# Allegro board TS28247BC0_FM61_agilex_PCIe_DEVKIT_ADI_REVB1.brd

Outline 274.32 x 111.15 mm; copper layers: TOP, L02_GND1, L03_SIG1, L04_GND2, L05_SIG2, L06_GND3, L07_SIG3, L08_GND4, L09_PWR1, L10_PWR2, L11_GND5, L12_SIG4, L13_GND6, L14_SIG5, L15_GND7, L16_SIG6, L17_GND8, BOTTOM. Coordinates in mm from the lower left corner of the outline.
Outline path: 0,111.15 0,4.5 15,4.5 15,12.75 33.35,12.75 33.35,4.5 41.35,4.5 41.35,10.92 arc(43.18,12.75) 45,10.92 45,0.5 45.5,0 55.7,0 56.2,0.5 56.2,7.45 arc(57.15,8.4) 58.1,7.45 58.1,0.5 58.6,0 128.8,0 129.3,0.5 129.3,7.62 arc(130.67,8.99) 132.04,7.62 132.04,3.45 132.55,2.95 143.35,2.95 144.74,5.32 144.74,7.95 140.78,7.95 arc(139.54,8.46) 139.03,9.7 139.03,11 arc(139.54,12.24) 140.78,12.75 274.32,12.75 274.32,111.15 0,111.15

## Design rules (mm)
constraint set DEFAULT: min track width 0.149
net group AS_CLK: nets AS_CLK AS_CLK_R
net group BUFFER_DIF0_: nets BUFFER_DIF0_N BUFFER_DIF0_P
net group BUFFER_DIF1_: nets BUFFER_DIF1_N BUFFER_DIF1_P
net group CLK_DDR4_CH0_N: nets CLK_DDR4_CH0_N SI5341_OUT3N
net group CLK_DDR4_CH0_P: nets CLK_DDR4_CH0_P SI5341_OUT3P
net group CLK_DDR4_CH1_N: nets CLK_DDR4_CH1_N SI5341_OUT1N
net group CLK_DDR4_CH1_P: nets CLK_DDR4_CH1_P SI5341_OUT1P
net group CLK_DDR4_CH2_N: nets CLK_DDR4_CH2_N SI5341_OUT4N
net group CLK_DDR4_CH2_P: nets CLK_DDR4_CH2_P SI5341_OUT4P
net group CLK_SYS_100M_N: nets CLK_SYS_100M_N SI5341_OUT6N
net group CLK_SYS_100M_P: nets CLK_SYS_100M_P SI5341_OUT6P
net group CLK_SYS_BAK_50M_N: nets CLK_SYS_BAK_50M_N SI5341_OUT7N
net group CLK_SYS_BAK_50M_P: nets CLK_SYS_BAK_50M_P SI5341_OUT7P
net group CORE_PMBUS_ALERTN: nets CORE_PMBUS_ALERTN LTM3888_ALERTN
net group CORE_PMBUS_SCL: nets CORE_PMBUS_SCL LTM3888_SCL
net group CORE_PMBUS_SDA: nets CORE_PMBUS_SDA LTM3888_SDA
net group DP_DDR3B_DQS_6: nets DDR4_DIMM_CH0_DQ43 VSS_SENSE
net group DP_FX2_D_: nets FX2_D_N FX2_D_P
net group DP_PCIE_REFCLK_: nets REFCLK_PCIE_EP_EDGE_N REFCLK_PCIE_EP_EDGE_P
net group DP_PEX_RX_0: nets PCIE_EP_TX_N0 PCIE_EP_TX_P0
net group DP_PEX_RX_1: nets PCIE_EP_TX_N1 PCIE_EP_TX_P1
net group DP_PEX_RX_2: nets PCIE_EP_TX_N2 PCIE_EP_TX_P2
net group DP_PEX_RX_3: nets PCIE_EP_TX_N3 PCIE_EP_TX_P3
net group DP_PEX_RX_4: nets PCIE_EP_TX_N4 PCIE_EP_TX_P4
net group DP_PEX_RX_5: nets PCIE_EP_TX_N5 PCIE_EP_TX_P5
net group DP_PEX_RX_6: nets PCIE_EP_TX_N6 PCIE_EP_TX_P6
net group DP_PEX_RX_7: nets PCIE_EP_TX_N7 PCIE_EP_TX_P7
net group DP_PEX_RX_8: nets PCIE_EP_TX_N8 PCIE_EP_TX_P8
net group DP_PEX_RX_9: nets PCIE_EP_TX_N9 PCIE_EP_TX_P9
net group DP_PEX_RX_10: nets PCIE_EP_TX_N10 PCIE_EP_TX_P10
net group DP_PEX_RX_11: nets PCIE_EP_TX_N11 PCIE_EP_TX_P11
net group DP_PEX_RX_12: nets PCIE_EP_TX_N12 PCIE_EP_TX_P12
net group DP_PEX_RX_13: nets PCIE_EP_TX_N13 PCIE_EP_TX_P13
net group DP_PEX_RX_14: nets PCIE_EP_TX_N14 PCIE_EP_TX_P14
net group DP_PEX_RX_15: nets PCIE_EP_TX_N15 PCIE_EP_TX_P15
net group DP_SI5341_OUT5: nets SI5341_OUT5N SI5341_OUT5P
net group EMMC_CMD: nets EMMC_CMD EMMC_COMMAND
net group EMMC_DAT0: nets EMMC_DAT0 EMMC_DATA0
net group EMMC_DAT1: nets EMMC_DAT1 EMMC_DATA1
net group EMMC_DAT2: nets EMMC_DAT2 EMMC_DATA2
net group EMMC_DAT3: nets EMMC_DAT3 EMMC_DATA3
net group EMMC_DAT4: nets EMMC_DAT4 EMMC_DATA4
net group EMMC_DAT5: nets EMMC_DAT5 EMMC_DATA5
net group EMMC_DAT6: nets EMMC_DAT6 EMMC_DATA6
net group EMMC_DAT7: nets EMMC_DAT7 EMMC_DATA7
net group ENET_GTX_CLK: nets ENET_GTX_CLK N35951471
net group ENET_RX_CLK: nets E_RX_CLK ENET_RX_CLK
net group ENET_RX_DV: nets E_RX_DV ENET_RX_DV
net group ENET_RXD0: nets E_RXD0 ENET_RXD0
net group ENET_RXD1: nets E_RXD1 ENET_RXD1
net group ENET_RXD2: nets E_RXD2 ENET_RXD2
net group ENET_RXD3: nets E_RXD3 ENET_RXD3
net group EXT_JTAG_TCK: nets EXT_JTAG_TCK N37926941
net group FM6_TEMP0: nets FPGA_TEMP0N FPGA_TEMP0P
net group FM6_TEMP1: nets FPGA_TEMP1N FPGA_TEMP1P
net group FM6_TEMP2: nets FPGA_TEMP2N FPGA_TEMP2P
net group FM6_TEMP3: nets FPGA_TEMP3N FPGA_TEMP3P
net group FPGA_OSC_CLK_1: nets FPGA_OSC_CLK_1 SI5341_OUT8P
net group GNDSENSE: nets GNDSENSE VCCLSENSE
net group LTM_SCL: nets LTM_SCL MAIN_I2C_SCL
net group LTM_SDA: nets LTM_SDA MAIN_I2C_SDA
net group MDI_HPS_0: nets MDI_HPS_N0 MDI_HPS_P0
net group MDI_HPS_1: nets MDI_HPS_N1 MDI_HPS_P1
net group MDI_HPS_2: nets MDI_HPS_N2 MDI_HPS_P2
net group MDI_HPS_3: nets MDI_HPS_N3 MDI_HPS_P3
net group N32053041: nets N32052935 N32053041
net group N36803169: nets N36803165 N36803169
net group N36803284: nets N36803267 N36803284
net group PCIE_EP_RX_CN0: nets PCIE_EP_RX_CN0 PCIE_EP_RX_N0
net group PCIE_EP_RX_CN1: nets PCIE_EP_RX_CN1 PCIE_EP_RX_N1
net group PCIE_EP_RX_CN2: nets PCIE_EP_RX_CN2 PCIE_EP_RX_N2
net group PCIE_EP_RX_CN3: nets PCIE_EP_RX_CN3 PCIE_EP_RX_N3
net group PCIE_EP_RX_CN4: nets PCIE_EP_RX_CN4 PCIE_EP_RX_N4
net group PCIE_EP_RX_CN6: nets PCIE_EP_RX_CN6 PCIE_EP_RX_N6
net group PCIE_EP_RX_CN7: nets PCIE_EP_RX_CN7 PCIE_EP_RX_N7
net group PCIE_EP_RX_CN8: nets PCIE_EP_RX_CN8 PCIE_EP_RX_N8
net group PCIE_EP_RX_CN9: nets PCIE_EP_RX_CN9 PCIE_EP_RX_N9
net group PCIE_EP_RX_CN10: nets PCIE_EP_RX_CN10 PCIE_EP_RX_N10
net group PCIE_EP_RX_CN11: nets PCIE_EP_RX_CN11 PCIE_EP_RX_N11
net group PCIE_EP_RX_CN12: nets PCIE_EP_RX_CN12 PCIE_EP_RX_N12
net group PCIE_EP_RX_CN13: nets PCIE_EP_RX_CN13 PCIE_EP_RX_N13
net group PCIE_EP_RX_CN15: nets PCIE_EP_RX_CN15 PCIE_EP_RX_N15
net group PCIE_EP_RX_CP0: nets PCIE_EP_RX_CP0 PCIE_EP_RX_P0
net group PCIE_EP_RX_CP1: nets PCIE_EP_RX_CP1 PCIE_EP_RX_P1
net group PCIE_EP_RX_CP2: nets PCIE_EP_RX_CP2 PCIE_EP_RX_P2
net group PCIE_EP_RX_CP3: nets PCIE_EP_RX_CP3 PCIE_EP_RX_P3
net group PCIE_EP_RX_CP4: nets PCIE_EP_RX_CP4 PCIE_EP_RX_P4
net group PCIE_EP_RX_CP5: nets PCIE_EP_RX_CP5 PCIE_EP_RX_P5
net group PCIE_EP_RX_CP6: nets PCIE_EP_RX_CP6 PCIE_EP_RX_P6
net group PCIE_EP_RX_CP7: nets PCIE_EP_RX_CP7 PCIE_EP_RX_P7
net group PCIE_EP_RX_CP8: nets PCIE_EP_RX_CP8 PCIE_EP_RX_P8
net group PCIE_EP_RX_CP9: nets PCIE_EP_RX_CP9 PCIE_EP_RX_P9
net group PCIE_EP_RX_CP10: nets PCIE_EP_RX_CP10 PCIE_EP_RX_P10
net group PCIE_EP_RX_CP11: nets PCIE_EP_RX_CP11 PCIE_EP_RX_P11
net group PCIE_EP_RX_CP12: nets PCIE_EP_RX_CP12 PCIE_EP_RX_P12
net group PCIE_EP_RX_CP13: nets PCIE_EP_RX_CP13 PCIE_EP_RX_P13
net group PCIE_EP_RX_CP14: nets PCIE_EP_RX_CP14 PCIE_EP_RX_P14
net group PCIE_EP_RX_CP15: nets PCIE_EP_RX_CP15 PCIE_EP_RX_P15
net group PWR_MAX10_JTAG_TCK: nets N31875930 PWR_MAX10_JTAG_TCK
net group PWR_MAX10_JTAG_TDI: nets N31875950 PWR_MAX10_JTAG_TDI
net group PWR_MAX10_JTAG_TDO: nets N31875960 PWR_MAX10_JTAG_TDO
net group PWR_MAX10_JTAG_TMS: nets N31875914 PWR_MAX10_JTAG_TMS
net group REFCLK_PCIE_EP_N: nets REFCLK_PCIE_EP_N SI2202_OUT0N
net group REFCLK_PCIE_EP_P: nets REFCLK_PCIE_EP_P SI2202_OUT0P
net group SI5341_OUT0: nets SI5341_OUT0N SI5341_OUT0P
net group UART_RX: nets N35980126 UART_RX
net group USB_UART_DP: nets USB_UART_DM USB_UART_DP
net group VOSNS-: nets VOSNS+ VOSNS-
net group 5MILS: nets 0P6V_DDR4_VTT_CH23_PG 0P6V_VTT_DDR4_CH01_PG 1P2V_DDR4_CH01_EN 1P2V_DDR4_CH01_PG 1P2V_DDR4_CH23_EN 1P2V_DDR4_CH23_PG 1P2V_PRE_PG 1P8V_EN 1P8V_PRE_PG 2P5V_EN 2P5V_PG 3P3V_EN 3P3V_PG 3P3V_STBY_PG 5V_PG 12V_G1_OV_PG 12V_G1_PG 12V_G1_UV_PG 12V_G2_PG FPGA_I2C_EN FPGA_PMBUS_EN FPGA_VCC_EN FPGA_VCC_PG HPS_I2C_EN IO_1P8V_EN IO_1P8V_PG IO_3P3V_EN MAIN_PMBUS_EN PWR_ENA VCC_HSSI_EN VCC_HSSI_PG VCCFUSEWR_EN VCCFUSEWR_PG VCCH_GXER1_EN VCCH_GXER1_PG VCCL_HPS_EN VCCL_HPS_PG VCCL_SDM_EN VCCL_SDM_PG VCCR_EN VCCR_PG VTT_DDR4_CH01_EN VTT_DDR4_CH23_EN
net group 8MILS: nets N31872869 N31873008 N31873076 N31873164 N31873322 N31873366 N32230759 N32408441 N32411786 TSENSE_ALERTN VCC_SENSE
net group CLK: nets REFCLK_156M_QSFPDD_N REFCLK_156M_QSFPDD_P REFCLK_322M_QSFPDD_N REFCLK_322M_QSFPDD_P REFCLK_PCIE_CH0_N REFCLK_PCIE_CH0_P REFCLK_PCIE_CH2_N REFCLK_PCIE_CH2_P
net group CLK_DDR4_CH3_N: nets CLK_DDR4_CH3_N
net group CLK_DDR4_CH3_P: nets CLK_DDR4_CH3_P
net group CLK_SE: nets CLK125_NDO_LED_MODE CLK_PWR_M10 CLK_UBII_M10 DDR4_DIMM_SCL DDR4_DIMM_SDA DDR4D_SCL DDR4D_SDA FPGA_I2C_SCL FPGA_I2C_SDA FPGA_SDM_SCL FPGA_SDM_SDA FX2_SCL FX2_SDA HPS_I2C_SCL HPS_I2C_SDA HPS_OSC_CLK MAX_SDA PCIE_1V2_CLKREQN PCIE_CLKREQN PCIE_EP_3V3_I2C_SCL PCIE_EP_3V3_I2C_SDA PCIE_EP_I2C_SCL PCIE_EP_I2C_SDA QSFPDD_FPGA_I2C_SCL QSFPDD_FPGA_I2C_SDA QSFPDD_I2C_SCL QSFPDD_I2C_SDA SD_CLK_3.3V USB_T_CLK
net group DDR4_DIMM_CH0_ADD: nets DDR4_DIMM_CH0_CK_N0 DDR4_DIMM_CH0_CK_N1 DDR4_DIMM_CH0_CK_P0 DDR4_DIMM_CH0_CK_P1 DDR4_DIMM_CH0_RZQ
net group DDR4_DIMM_CH1_ADD: nets DDR4_DIMM_CH1_RZQ
net group DDR4_DIMM_CH1_CK_N0: nets DDR4_DIMM_CH1_CK_N1
net group DDR4_DIMM_CH1_CK_P0: nets DDR4_DIMM_CH1_CK_P1
net group DDR4_DIMM_CH2_ADD: nets DDR4_DIMM_CH2_RZQ
net group DDR4_DIMM_CH3_ADD: nets DDR4_DIMM_CH3_RZQ
net group ENET_VDD1.2V: nets N35952937
net group MICTOR_JTAG_TCK: nets HPS_JTAG_TCK
net group MICTOR_JTAG_TDI: nets HPS_JTAG_TDI
net group MICTOR_JTAG_TDO: nets HPS_JTAG_TDO
net group MICTOR_JTAG_TMS: nets HPS_JTAG_TMS
net group PCIE_EP_JTAG_TCK: nets N31093028
net group POWER_ON: nets N32233467 N32408103 POWER_ON
net group PWR: nets 0P6V_VREF_DDR4_CH23 1P2V_DDR4_CH01_AGND 1P2V_DDR4_CH23_AGND ACTIVITY_LED IO_1P8V_AGND LINK_LED LT4625_INTVCC N34525726 N35660053 N35951410 N35951814 N37761614 N37761618 USB_UART_CON_5V VBUS_5V VCCAPLL_AGND VCCH_GXER1_AGND VDD33_OUT1 VREF_B
net group QSFPDD: nets QSFPDD0_RX0_N QSFPDD0_RX0_P QSFPDD0_RX1_N QSFPDD0_RX1_P QSFPDD0_RX4_N QSFPDD0_RX4_P QSFPDD0_RX6_N QSFPDD0_RX6_P QSFPDD0_RX7_N QSFPDD0_RX7_P QSFPDD0_TX2_N QSFPDD0_TX2_P QSFPDD0_TX4_N QSFPDD0_TX4_P QSFPDD0_TX6_N QSFPDD0_TX6_P QSFPDD0_TX7_N QSFPDD0_TX7_P QSFPDD1_RX0_N QSFPDD1_RX0_P QSFPDD1_RX1_N QSFPDD1_RX1_P QSFPDD1_RX3_N QSFPDD1_RX3_P QSFPDD1_RX4_N QSFPDD1_RX4_P QSFPDD1_RX6_N QSFPDD1_RX6_P QSFPDD1_TX0_N QSFPDD1_TX0_P QSFPDD1_TX2_N QSFPDD1_TX2_P QSFPDD1_TX3_N QSFPDD1_TX3_P QSFPDD1_TX4_N QSFPDD1_TX4_P QSFPDD1_TX5_N QSFPDD1_TX5_P QSFPDD1_TX6_N QSFPDD1_TX6_P QSFPDD1_TX7_N QSFPDD1_TX7_P
net group SENSE: nets N31872899 N31873240 N31873414

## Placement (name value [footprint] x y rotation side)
B1  Molex_QSFPDD_Cage  [MOLEX_QSFPDD_CAGE]  40.1 77.59 90 top
B2  Molex_QSFPDD_Cage  [MOLEX_QSFPDD_CAGE]  40.1 52.8 90 top
C1  1uF  [0402]  105.42 104.35 90 bottom
C2  0.1uF  [0402]  105.42 103.46 90 bottom
C3  0.1uF  [0402]  106.31 93.68 270 bottom
C4  10nF  [0402]  144.39 95.86 180 bottom
C5  0.1uF  [0402]  125.69 95.86 180 bottom
C6  10nF  [0402]  142.69 93.04 0 bottom
C7  0.1uF  [0402]  123.15 95.86 180 bottom
C8  10nF  [0402]  142.7 95.86 180 bottom
C9  0.1uF  [0402]  140.98 93.04 0 bottom
C10  10nF  [0402]  119.74 93.02 0 bottom
C11  0.1uF  [0402]  140.14 95.86 180 bottom
C12  10nF  [0402]  126.7 95.86 180 bottom
C13  0.1uF  [0402]  124.85 93.02 0 bottom
C14  10nF  [0402]  117.23 93.04 0 bottom
C15  0.1uF  [0402]  138.44 93.04 0 bottom
C16  100uF  [1206]  127.83 93.68 0 bottom
C17  1uF  [0402]  131.3 97.36 270 bottom
C18  0.1uF  [0402]  65.54 97.49 90 bottom
C19  0.1uF  [0402]  131.33 93.42 270 bottom
C20  100uF  [1206]  116.34 95.76 0 bottom
C21  100uF  [1206]  148.6 96.01 180 bottom
C22  10uF  [1210]  148.6 93.22 0 bottom
C23  10uF  [1210]  111.13 94.41 180 bottom
C24  0.1uF  [0402]  67.06 98 0 bottom
C25  0.1uF  [0402]  138.21 95.86 180 bottom
C26  0.1uF  [0402]  122.28 93.02 0 bottom
C27  10nF  [0402]  145.24 93.02 0 bottom
C28  10nF  [0402]  120.61 95.86 180 bottom
C29  10nF  [0402]  131.33 92.15 270 bottom
C31  0.1uF  [0402]  131.3 96.09 270 bottom
C32  100uF  [1206]  188.35 95.46 0 bottom
C33  10uF  [1210]  182.89 94.59 180 bottom
C34  0.1uF  [0402]  192.03 93.03 0 bottom
C35  10nF  [0402]  191.09 93.03 0 bottom
C37  1uF  [0402]  96.15 104.09 90 bottom
C38  0.1uF  [0402]  96.15 103.08 90 bottom
C39  0.1uF  [0402]  97.04 93.68 270 bottom
C40  10nF  [0402]  145.24 100.64 0 bottom
C41  0.1uF  [0402]  122.28 100.64 0 bottom
C42  10nF  [0402]  125.69 103.48 180 bottom
C43  0.1uF  [0402]  126.7 103.48 180 bottom
C44  10nF  [0402]  142.69 100.66 0 bottom
C45  0.1uF  [0402]  124.85 100.64 0 bottom
C46  10nF  [0402]  120.61 103.48 180 bottom
C47  0.1uF  [0402]  138.21 103.48 180 bottom
C48  10nF  [0402]  119.74 100.64 0 bottom
C49  0.1uF  [0402]  138.44 100.66 0 bottom
C50  10nF  [0402]  117.18 100.64 0 bottom
C51  0.1uF  [0402]  123.15 103.48 180 bottom
C52  100uF  [1206]  127.64 98 0 bottom
C53  1uF  [0402]  131.38 104.98 270 bottom
C54  0.1uF  [0402]  67.44 104.85 90 bottom
C55  0.1uF  [0402]  131.3 99.14 270 bottom
C57  10nF  [0402]  131.3 100.41 270 bottom
C58  0.1uF  [0402]  140.14 103.48 180 bottom
C60  0.1uF  [0402]  131.38 103.71 270 bottom
C61  100uF  [1206]  188.35 103.08 0 bottom
C62  10uF  [1210]  183.01 102.09 180 bottom
C63  0.1uF  [0402]  192.03 100.65 0 bottom
C64  10nF  [0402]  191.09 100.65 0 bottom
C65  100uF  [1206]  148.6 103.33 180 bottom
C66  100uF  [1206]  116.34 103.38 0 bottom
C67  10uF  [1210]  111.26 102.03 180 bottom
C68  10uF  [1210]  148.6 100.41 0 bottom
C69  0.1uF  [0402]  140.98 100.66 0 bottom
C70  10nF  [0402]  142.7 103.48 180 bottom
C71  10nF  [0402]  144.39 103.48 180 bottom
C73  1uF  [0402]  151.52 20.65 180 bottom
C74  0.1uF  [0402]  152.53 20.65 180 bottom
C75  0.1uF  [0402]  152.53 30.69 0 bottom
C76  10nF  [0402]  113.79 30.94 180 bottom
C77  0.1uF  [0402]  136.75 30.91 180 bottom
C78  10nF  [0402]  114.65 27.92 0 bottom
C79  0.1uF  [0402]  133.35 27.92 0 bottom
C80  10nF  [0402]  116.34 30.91 180 bottom
C81  0.1uF  [0402]  118.9 27.92 0 bottom
C82  10nF  [0402]  116.33 27.92 0 bottom
C83  0.1uF  [0402]  134.19 30.91 180 bottom
C84  10nF  [0402]  135.89 27.92 0 bottom
C85  0.1uF  [0402]  120.6 30.91 180 bottom
C86  10nF  [0402]  138.43 27.92 0 bottom
C87  0.1uF  [0402]  132.33 27.92 0 bottom
C88  100uF  [1206]  131.2 30.05 180 bottom
C89  1uF  [0402]  127.73 27.38 90 bottom
C90  0.1uF  [0402]  193.56 26.3 270 bottom
C91  0.1uF  [0402]  127.73 31.32 90 bottom
C92  100uF  [1206]  142.7 28.1 180 bottom
C93  100uF  [1206]  110.37 27.66 0 bottom
C94  10uF  [1210]  110.37 30.56 180 bottom
C95  10uF  [1210]  147.71 29.42 0 bottom
C96  0.1uF  [0402]  120.83 27.92 0 bottom
C97  0.1uF  [0402]  118.06 30.91 180 bottom
C98  10nF  [0402]  141.86 30.91 180 bottom
C99  10nF  [0402]  139.29 30.91 180 bottom
C100  0.1uF  [0402]  191.59 26.3 90 bottom
C101  10nF  [0402]  127.73 32.21 90 bottom
C103  0.1uF  [0402]  127.73 26.49 90 bottom
C104  100uF  [1206]  70.69 28.4 180 bottom
C105  10uF  [1210]  75.95 29.39 0 bottom
C106  0.1uF  [0402]  67.94 30.83 180 bottom
C107  10nF  [0402]  67 30.83 180 bottom
C109  10nF  [0402]  114.65 20.3 0 bottom
C110  0.1uF  [0402]  118.06 23.29 180 bottom
C111  10nF  [0402]  116.33 20.3 0 bottom
C112  0.1uF  [0402]  120.6 23.29 180 bottom
C113  10nF  [0402]  116.34 23.29 180 bottom
C114  0.1uF  [0402]  118.9 20.3 0 bottom
C115  10nF  [0402]  113.79 23.32 180 bottom
C116  0.1uF  [0402]  120.83 20.3 0 bottom
C117  10nF  [0402]  135.89 20.3 0 bottom
C118  0.1uF  [0402]  134.19 23.29 180 bottom
C119  10nF  [0402]  138.43 20.3 0 bottom
C120  0.1uF  [0402]  132.33 20.3 0 bottom
C121  100uF  [1206]  131.2 22.43 180 bottom
C122  1uF  [0402]  127.73 24.72 90 bottom
C123  0.1uF  [0402]  193.56 18.76 270 bottom
C124  0.1uF  [0402]  127.73 23.83 90 bottom
C125  100uF  [1206]  110.37 20.04 0 bottom
C126  100uF  [1206]  142.7 20.48 180 bottom
C127  10uF  [1210]  110.37 22.94 180 bottom
C128  10uF  [1210]  147.84 21.8 0 bottom
C129  0.1uF  [0402]  136.75 23.29 180 bottom
C130  0.1uF  [0402]  133.35 20.3 0 bottom
C131  10nF  [0402]  141.86 23.29 180 bottom
C132  10nF  [0402]  139.29 23.29 180 bottom
C133  0.1uF  [0402]  191.59 18.76 90 bottom
C134  10nF  [0402]  129.04 18.11 270 bottom
C136  0.1uF  [0402]  127.73 19.76 90 bottom
C137  100uF  [1206]  70.87 20.78 180 bottom
C138  10uF  [1210]  75.95 21.8 0 bottom
C139  0.1uF  [0402]  67.95 23.19 180 bottom
C140  10nF  [0402]  67.01 23.19 180 bottom
C142  0.1uF  [0402]  44.08 66.37 0 bottom
C143  22uF  [0603]  44.33 68.91 90 bottom
C144  0.1uF  [0402]  56.52 67.01 180 bottom
C145  10uF  [0603]  55 67.01 90 bottom
C146  22uF  [0603]  53.22 65.36 90 bottom
C147  22uF  [0603]  50.81 65.36 90 bottom
C148  0.1uF  [0402]  51.82 69.17 0 bottom
C149  10uF  [0603]  46.87 68.15 0 bottom
C150  22uF  [0603]  46.87 69.93 0 bottom
C151  22uF  [0603]  50.55 69.17 270 bottom
C152  0.1uF  [0402]  57.41 70.18 0 bottom
C153  10uF  [0603]  56.01 70.82 270 bottom
C154  22uF  [0603]  54.49 75.39 180 bottom
C155  22uF  [0603]  54.49 73.87 180 bottom
C156  1000pF  [1206]  19.82 57.99 270 bottom
C157  0.1uF  [0402]  44.08 41.61 0 bottom
C158  22uF  [0603]  44.33 44.15 90 bottom
C159  0.1uF  [0402]  56.17 42.34 180 bottom
C160  10uF  [0603]  55 42.24 90 bottom
C161  22uF  [0603]  50.6 40.52 90 bottom
C162  22uF  [0603]  53.22 40.59 90 bottom
C163  0.1uF  [0402]  50.81 44.4 0 bottom
C164  10uF  [0603]  49.41 44.53 270 bottom
C165  22uF  [0603]  46.87 43.39 0 bottom
C166  22uF  [0603]  46.87 44.91 0 bottom
C167  0.1uF  [0402]  57.41 45.42 0 bottom
C168  10uF  [0603]  56.01 46.05 270 bottom
C169  22uF  [0603]  54.49 49.1 180 bottom
C170  22uF  [0603]  54.49 50.62 180 bottom
C171  1000pF  [1206]  24.39 53.42 90 bottom
C172  0.22uF  [0402]  62.66 10.98 0 bottom
C173  1uF  [0402]  80.14 20.65 180 bottom
C174  0.1uF  [0402]  81.03 20.65 180 bottom
C175  0.22uF  [0402]  63.66 10.98 0 bottom
C176  0.1uF  [0402]  81.03 30.56 0 bottom
C177  0.22uF  [0402]  67.66 10.98 0 bottom
C178  0.22uF  [0402]  68.66 10.98 0 bottom
C179  0.22uF  [0402]  71.66 10.98 0 bottom
C180  0.22uF  [0402]  72.66 10.98 0 bottom
C181  0.22uF  [0402]  75.66 10.98 0 bottom
C182  0.22uF  [0402]  76.66 10.98 0 bottom
C183  0.22uF  [0402]  81.66 10.98 0 bottom
C184  0.22uF  [0402]  82.66 10.98 0 bottom
C185  0.22uF  [0402]  85.66 10.98 0 bottom
C186  0.22uF  [0402]  86.66 10.98 0 bottom
C187  0.22uF  [0402]  89.66 10.98 0 bottom
C188  0.22uF  [0402]  90.66 10.98 0 bottom
C189  0.22uF  [0402]  93.66 10.98 0 bottom
C190  0.22uF  [0402]  94.66 10.98 0 bottom
C191  0.22uF  [0402]  98.66 10.98 0 bottom
C192  0.22uF  [0402]  99.66 10.98 0 bottom
C193  0.22uF  [0402]  102.66 10.98 0 bottom
C194  0.22uF  [0402]  103.66 10.98 0 bottom
C195  0.22uF  [0402]  106.66 10.98 0 bottom
C196  0.22uF  [0402]  107.66 10.98 0 bottom
C197  0.22uF  [0402]  110.66 10.98 0 bottom
C198  0.22uF  [0402]  111.66 10.98 0 bottom
C199  0.22uF  [0402]  114.66 10.98 0 bottom
C200  0.22uF  [0402]  115.66 10.98 0 bottom
C201  0.22uF  [0402]  118.66 10.98 0 bottom
C202  0.22uF  [0402]  119.66 10.98 0 bottom
C203  0.22uF  [0402]  122.66 10.98 0 bottom
C204  0.22uF  [0402]  123.66 10.98 0 bottom
C205  0.22uF  [0402]  126.66 10.98 0 bottom
C206  0.22uF  [0402]  127.66 10.98 0 bottom
C207  0.1uF  [0402]  209.01 32.09 0 bottom
C208  0.1uF  [0402]  208.01 29.49 0 bottom
C209  0.1uF  [0402]  203.33 28.08 0 bottom
C210  0.1uF  [0402]  2.93 88.47 270 bottom
C211  10nF  [0402]  12.33 90.25 90 bottom
C212  10nF  [0402]  12.33 89.23 90 bottom
C213  10nF  [0402]  19.57 80.6 270 bottom
C214  10nF  [0402]  21.34 80.6 270 bottom
C215  0.1uF  [0402]  2.93 91.14 90 bottom
C216  22uF  [0603]  35.06 82.63 270 bottom
C217  0.1uF  [0402]  25.79 88.39 180 top
C218  0.1uF  [0402]  32.01 92.03 180 bottom
C219  22uF  [0603]  15.5 76.91 270 bottom
C220  0.1uF  [0402]  25.5 86.2 0 top
C221  0.1uF  [0402]  26.9 84.8 0 top
C222  0.1uF  [0402]  29.73 87.71 90 top
C223  22uF  [0603]  17.79 80.85 270 bottom
C224  10nF  [0402]  24.45 87.54 270 top
C225  120pF  [0402]  49.28 93.93 180 bottom
C226  10nF  [0402]  36.96 92.03 0 bottom
C227  10nF  [0402]  39.76 91.98 180 bottom
C228  10nF  [0402]  38.87 91.98 180 bottom
C229  22uF  [0603]  55.38 91.77 180 bottom
C230  22uF  [0603]  27.99 88.74 270 top
C231  10nF  [0402]  26.68 88.39 180 top
C232  10nF  [0402]  29.73 89.99 270 top
C233  22uF  [0603]  52.33 91.77 0 bottom
C234  2.2uF  [0603]  52.33 91.77 0 top
C235  1nF  [0402]  56.52 96.47 180 bottom
C236  22uF  [0603]  38.11 82.63 270 bottom
C237  0.1uF  [0402]  29.73 84.91 90 top
C238  0.1uF  [0402]  28.17 84.8 0 top
C239  0.1uF  [0402]  29.73 88.6 90 top
C240  0.1uF  [0402]  29.73 86.69 90 top
C241  0.1uF  [0402]  29.73 83.96 90 top
C242  0.1uF  [0402]  25.5 84.16 180 top
C243  0.1uF  [0402]  28.84 66.37 270 bottom
C244  0.1uF  [0402]  15.5 70.44 180 bottom
C245  39pF  [0402]  22.66 74.63 270 bottom
C246  39pF  [0402]  20.76 74.63 90 bottom
C247  0.1uF  [0402]  26.68 75.01 0 bottom
C248  DNI  [0402]  14.1 104.6 0 bottom
C249  0.1uF  [0402]  24.14 75.39 180 bottom
C250  2.2uF  [0603]  25.41 75.52 90 bottom
C251  0.1uF  [0402]  16.26 68.91 270 bottom
C252  2.2uF  [0603]  18.8 66.75 0 bottom
C253  22uF  [0603]  28.84 74.25 0 bottom
C254  0.1uF  [0402]  25.03 71.07 90 bottom
C255  4.7uF  [0805]  28.07 69.42 270 bottom
C256  10nF  [0402]  17.91 107.01 0 bottom
C257  22uF  [0603]  17.91 104.47 180 bottom
C258  0.1uF  [0402]  47.25 90.63 0 bottom
C259  0.1uF  [0402]  38.74 98.5 90 bottom
C260  0.1uF  [0402]  49.79 98.12 90 bottom
C261  2.2uF  [0603]  40.52 94.95 270 bottom
C262  0.1uF  [0402]  38.74 95.96 90 bottom
C263  0.1uF  [0402]  41.16 107.65 180 bottom
C264  2.2uF  [0603]  46.49 106.12 270 bottom
C265  1uF  [0603]  30.36 108.28 0 bottom
C266  0.1uF  [0402]  28.33 108.28 180 bottom
C267  2.2uF  [0603]  40.52 98.12 270 bottom
C268  0.22uF  [0402]  34.04 92.03 180 bottom
C269  0.22uF  [0402]  28.2 92.41 270 bottom
C270  2.2uF  [0603]  39.76 107.65 90 bottom
C271  0.22uF  [0402]  39.76 104.66 0 bottom
C272  0.22uF  [0402]  38.23 104.22 270 bottom
C273  0.22uF  [0402]  38.23 105.06 270 bottom
C274  0.1uF  [0402]  111.01 62.18 120 bottom
C275  1uF  [0201]  129.33 59.1 150 bottom
C276  1uF  [0201]  127.6 59.1 150 bottom
C277  1uF  [0201]  103.96 64.1 210 bottom
C278  1uF  [0201]  108.55 70.75 210 bottom
C279  1uF  [0201]  108.85 72.28 90 bottom
C280  1uF  [0201]  127.9 51.51 270 bottom
C281  1uF  [0201]  128.21 53.1 30 bottom
C282  1uF  [0201]  103.09 60.6 30 bottom
C283  1uF  [0201]  103.09 59.6 30 bottom
C284  0.1uF  [0402]  122.23 72.65 300 bottom
C285  0.1uF  [0402]  120.49 72.65 300 bottom
C286  0.1uF  [0402]  104.08 72.01 90 bottom
C287  0.1uF  [0402]  104.08 72.8 90 bottom
C289  1uF  [0201]  129.07 52.6 210 bottom
C290  1uF  [0201]  129.33 51.1 330 bottom
C291  1uF  [0201]  107.68 71.6 150 bottom
C292  1uF  [0201]  107.68 72.6 150 bottom
C293  1uF  [0201]  131.91 53.24 30 bottom
C294  0.1uF  [0402]  111.06 51.21 120 bottom
C295  0.1uF  [0402]  109.33 51.21 120 bottom
C296  0.1uF  [0402]  120.49 51.21 240 bottom
C297  0.1uF  [0402]  122.23 51.21 240 bottom
C298  1uF  [0402]  47.07 29.06 180 bottom
C299  1uF  [0402]  46.18 29.06 180 bottom
C300  1uF  [0402]  52.18 22.91 0 bottom
C301  1uF  [0402]  52.97 28.27 180 bottom
C302  1uF  [0402]  47.51 22.91 0 bottom
C303  1uF  [0402]  51.85 25.73 90 bottom
C304  1uF  [0402]  42.62 22.3 180 bottom
C305  1uF  [0402]  44.84 23.07 270 bottom
C306  1uF  [0402]  44.84 24.08 270 bottom
C307  1uF  [0402]  51.7 29.03 180 bottom
C308  1uF  [0402]  51.85 24.46 90 bottom
C309  1uF  [0402]  53.09 22.91 0 bottom
C310  1uF  [0402]  50.98 22.91 0 bottom
C311  1uF  [0402]  50.48 29.06 180 bottom
C312  1uF  [0402]  48.52 29.06 180 bottom
C313  1uF  [0402]  49.54 22.91 0 bottom
C314  1uF  [0402]  51.85 26.62 90 bottom
C315  0.1uF  [0402]  48.66 19.25 0 top
C316  0.1uF  [0402]  47.65 19.25 0 top
C317  0.1uF  [0402]  55.51 27.13 90 top
C318  0.1uF  [0402]  55.51 26.11 90 top
C319  18pF  [0402]  213.75 102.69 0 top
C320  0.1uF  [0402]  209.86 105.34 180 bottom
C321  0.1uF  [0402]  211.46 101.42 270 bottom
C322  0.1uF  [0402]  212.35 104.6 0 bottom
C323  0.1uF  [0402]  209.68 102.44 270 bottom
C324  18pF  [0402]  213.75 104.47 180 top
C325  4.7uF  [0402]  39.12 47.01 0 bottom
C326  0.1uF  [0402]  38.11 47.01 0 bottom
C327  0.1uF  [0402]  27.06 49.48 270 bottom
C328  0.1uF  [0402]  31.12 49.48 90 bottom
C329  0.1uF  [0402]  19.18 49.48 90 bottom
C330  0.1uF  [0402]  15.12 49.48 270 bottom
C331  0.1uF  [0402]  21.09 49.48 270 bottom
C332  0.1uF  [0402]  25.15 49.48 90 bottom
C333  0.1uF  [0402]  91.07 93.68 270 bottom
C334  0.1uF  [0402]  90.56 103.58 180 bottom
C335  0.1uF  [0402]  269.5 64.47 180 bottom
C336  1000pF  [0402]  265.56 59.13 90 bottom
C337  1000pF  [0402]  264.68 55.07 90 bottom
C338  1000pF  [0402]  264.68 51.01 90 bottom
C339  DNI  [1206]  263.18 104.32 270 bottom
C340  0.1uF  [0402]  21.01 30.43 0 top
C341  4.7nF  [0402]  3.03 18.37 180 bottom
C342  12pF  [0402]  13.79 20.6 90 top
C343  12pF  [0402]  11.95 20.6 270 top
C344  0.1uF  [0402]  32.77 45.16 90 bottom
C345  0.1uF  [0402]  10.87 28.86 270 bottom
C346  22uF  [0603]  9.91 19.38 270 top
C347  0.1uF  [0402]  9.66 24.34 0 bottom
C348  0.1uF  [0402]  10.23 29.82 270 bottom
C349  0.1uF  [0402]  16.11 30.18 180 bottom
C350  0.1uF  [0402]  18.61 29.32 90 bottom
C351  0.1uF  [0402]  18.61 24.32 90 bottom
C352  0.1uF  [0402]  16.11 22.37 0 bottom
C353  0.1uF  [0402]  14.36 23.64 0 bottom
C354  0.1uF  [0402]  12.07 23.64 0 bottom
C355  DNI  [0402]  35.44 29.72 180 bottom
C356  10uF  [0603]  22.23 30.43 0 bottom
C357  0.1uF  [0402]  28.03 24.42 90 bottom
C358  0.1uF  [0402]  32.03 26.75 270 bottom
C359  0.1uF  [0402]  32.83 27.71 270 bottom
C360  0.1uF  [0402]  34.43 24.83 45 bottom
C361  0.1uF  [0402]  31.23 25.06 90 bottom
C362  0.1uF  [0402]  36.33 29.72 0 bottom
C363  0.1uF  [0402]  22.36 29.03 90 bottom
C364  0.1uF  [0402]  26.43 28.55 270 bottom
C365  0.1uF  [0402]  32.83 20.42 270 bottom
C366  0.1uF  [0402]  30.51 17.62 90 bottom
C367  0.1uF  [0402]  30.83 20.02 180 bottom
C368  10uF  [0603]  28.09 29.86 0 bottom
C369  0.1uF  [0402]  26.03 24.82 0 bottom
C370  0.1uF  [0402]  35.23 22.82 270 bottom
C371  0.1uF  [0402]  31.63 23.23 0 bottom
C372  0.1uF  [0402]  26.03 27.22 0 bottom
C373  0.1uF  [0402]  31.88 29.72 0 bottom
C374  0.1uF  [0402]  26.03 22.42 180 bottom
C375  0.1uF  [0402]  36.84 28.32 90 bottom
C376  0.1uF  [0402]  34.43 26.83 270 bottom
C377  0.1uF  [0402]  29.63 26.03 270 bottom
C378  0.1uF  [0402]  28.83 22.03 90 bottom
C379  0.1uF  [0402]  37.23 20.82 180 bottom
C380  10uF  [0603]  24.65 25.48 90 bottom
C381  0.1uF  [0402]  37.23 23.23 180 bottom
C382  0.1uF  [0402]  253.63 36.02 0 bottom
C383  1pF  [0402]  255.66 36.02 0 bottom
C384  1pF  [0402]  255.66 34.11 0 bottom
C385  1pF  [0402]  257.69 36.02 0 bottom
C386  1pF  [0402]  251.59 36.02 0 bottom
C387  1pF  [0402]  259.72 36.02 0 bottom
C388  1pF  [0402]  257.69 34.11 0 bottom
C389  1pF  [0402]  259.72 34.11 0 bottom
C390  1pF  [0402]  251.59 34.11 0 bottom
C391  1pF  [0402]  253.63 34.11 0 bottom
C393  0.1uF  [0402]  249.44 65.23 270 top
C394  10uF  [0603]  247.68 67.29 0 top
C395  100pF  [0402]  74.3 81.49 270 top
C396  0.1uF  [0402]  73.03 88.03 180 bottom
C397  10uF  [0603]  262.29 33.48 270 bottom
C398  0.1uF  [0402]  254.95 31.06 0 bottom
C399  0.1uF  [0402]  250.95 26.26 0 bottom
C400  0.1uF  [0402]  247.66 24.59 270 bottom
C401  0.1uF  [0402]  253.35 23.86 0 bottom
C402  0.1uF  [0402]  251.21 20.91 0 bottom
C403  0.1uF  [0402]  260.23 29.29 90 bottom
C404  0.1uF  [0402]  257.75 26.66 90 bottom
C405  10uF  [0603]  257.75 21.41 180 bottom
C406  10uF  [0603]  254.64 21.41 180 bottom
C407  0.1uF  [0402]  260.23 22.18 90 bottom
C408  0.1uF  [0402]  256.55 29.46 0 bottom
C409  0.1uF  [0402]  252.23 20.91 0 bottom
C410  0.1uF  [0402]  247.66 28.65 270 bottom
C411  0.1uF  [0402]  254.55 27.46 270 bottom
C412  0.1uF  [0402]  250.55 28.26 270 bottom
C413  0.1uF  [0402]  255.35 24.26 90 bottom
C414  0.1uF  [0402]  260.23 26.24 90 bottom
C415  0.1uF  [0402]  247.66 32.72 270 bottom
C416  0.1uF  [0402]  252.47 30.26 0 bottom
C417  680pF  [0402]  265.79 89.08 90 bottom
C418  1uF  [0402]  265.79 88.22 270 bottom
C419  22uF  [1206]  238.94 101.55 270 bottom
C420  4.7nF  [0402]  247.25 97.73 0 bottom
C421  560uF  [8MM_CAN]  205.4 71.02 0 top
C422  22uF  [1206]  236.94 101.53 270 bottom
C423  22uF  [1206]  243.06 101.63 270 bottom
C424  22uF  [1206]  241.03 101.58 270 bottom
C425  DNI  [7343P]  251.86 100.99 90 top
C426  4.7nF  [0402]  247.1 91.11 90 top
C427  1.5uF  [1206]  247.3 84.1 180 bottom
C428  150uF  [7343P]  240.6 89.18 270 top
C429  150uF  [7343P]  246.95 100.66 90 top
C430  150uF  [7343P]  242.04 100.99 90 top
C431  150uF  [7343P]  198.59 71.3 270 top
C432  0.01uF  [0402]  240.62 84.66 180 bottom
C433  150uF  [7343P]  258.33 71.71 270 top
C434  4.7nF  [0402]  251.59 78.16 90 bottom
C435  DNI  [7343P]  245.07 81.03 180 top
C436  150uF  [7343P]  247.53 72.72 270 top
C437  150uF  [7343P]  242.2 72.72 270 top
C438  150uF  [7343P]  244.69 59.5 0 top
C439  150uF  [7343P]  252.86 72.72 270 top
C440  150uF  [7343P]  247.53 72.72 270 bottom
C441  150uF  [7343P]  218.12 57.69 270 top
C442  0.1uF  [0402]  254.9 55.96 0 top
C443  1uF  [0402]  247.91 55.22 90 bottom
C444  0.1uF  [0402]  245.24 54.56 0 bottom
C445  22uF  [1206]  250.83 55.58 90 bottom
C446  22uF  [1206]  250.83 55.58 90 top
C447  22uF  [1206]  253.37 55.58 90 top
C448  12pF  [0402]  240.93 50.76 270 bottom
C449  47uF  [1206]  250.83 50.75 90 bottom
C450  47uF  [1206]  253.37 50.75 90 bottom
C451  47uF  [1206]  253.37 50.75 90 top
C452  47uF  [1206]  250.83 50.75 90 top
C453  100pF  [0402]  245.37 49.53 90 top
C454  0.1uF  [0402]  240.93 51.67 270 bottom
C455  DNI  [C0402]  242.64 48.08 90 top
C456  22uF  [0603]  251.21 39.7 0 top
C457  22uF  [0603]  28.54 42.99 270 bottom
C458  47pF  [0402]  258.22 42.05 0 top
C459  47pF  [0402]  26.76 37.02 270 bottom
C460  22uF  [0603]  254.26 38.18 180 top
C461  22uF  [0603]  254.26 39.58 180 bottom
C462  22uF  [0603]  254.26 39.7 180 top
C463  22uF  [0603]  28.54 39.94 90 bottom
C464  22uF  [0603]  30.11 39.96 90 bottom
C465  22uF  [0603]  30.11 43 270 bottom
C466  10nF  [0402]  252.2 44.73 90 top
C467  10nF  [0402]  23.63 43.89 90 bottom
C555  22uF  [0603]  211.46 53.5 180 top
C557  47pF  [0402]  205.25 51.81 180 top
C558  22uF  [0603]  205.8 53.42 180 bottom
C559  22uF  [0603]  208.64 53.42 0 bottom
C560  22uF  [0603]  205.8 53.42 180 top
C561  10nF  [0402]  211.21 49.05 270 top
C652  2.2uF  [0402]  50.55 107.39 90 bottom
C653  22uF  [0603]  52.71 100.41 180 bottom
C654  22uF  [0603]  55.89 100.41 0 bottom
C655  22uF  [0603]  55.89 101.93 0 bottom
C656  22uF  [0603]  55.89 105.11 0 bottom
C657  22uF  [0603]  55.89 106.76 0 bottom
C658  0.1uF  [0402]  48.65 102.06 180 bottom
C659  22uF  [0603]  55.89 103.46 0 bottom
C660  10nF  [0402]  52.97 108.16 90 bottom
C661  2.2uF  [0402]  208.6 17.14 270 bottom
C662  22uF  [0603]  203.26 24 180 top
C663  22uF  [0603]  203.26 22.47 180 bottom
C664  22uF  [0603]  203.26 22.47 180 top
C665  22uF  [0603]  203.26 20.95 180 top
C666  22uF  [0603]  203.26 24 180 bottom
C667  22uF  [0603]  206.44 24 0 top
C668  22uF  [0603]  203.26 19.3 180 bottom
C669  22uF  [0603]  203.26 17.65 180 bottom
C670  22uF  [0603]  206.44 24 0 bottom
C671  22uF  [0603]  203.26 20.95 180 bottom
C672  0.1uF  [0402]  210.95 22.22 0 bottom
C673  10nF  [0402]  207.2 16.25 270 bottom
C679  100uF  [B2]  40.77 65.23 270 bottom
C680  DNI  [1210]  37.22 65.23 270 bottom
C681  0.047uF  [0402]  34.61 68.53 90 bottom
C682  22uF  [0603]  20.28 42.99 270 bottom
C683  270pF  [0402]  18.5 37.04 270 bottom
C684  22uF  [0603]  21.85 43 270 bottom
C685  22uF  [0603]  21.85 39.96 90 bottom
C686  22uF  [0603]  20.28 39.94 90 bottom
C687  10nF  [0402]  15.37 43.89 90 bottom
C702  0.1uF  [0402]  76.33 93.3 180 bottom
C703  0.1uF  [0402]  76.08 103.58 180 bottom
C704  0.1uF  [0402]  83.95 93.3 180 bottom
C705  0.1uF  [0402]  83.7 103.58 180 bottom
C706  1000pF  [1206]  7.75 77.8 270 bottom
C707  4.7uF  [0402]  209.68 103.33 270 bottom
C708  0.1uF  [0402]  26.67 17.62 270 bottom
C709  100pF  [0402]  76.21 81.49 270 top
C710  100pF  [0402]  70.49 81.49 90 top
C711  100pF  [0402]  72.4 81.49 90 top
C737  1uF  [0201]  123.01 55.1 30 bottom
C762  4.7uF  [0402]  124.05 60.15 60 bottom
C763  4.7uF  [0402]  118.86 53.71 120 bottom
C764  4.7uF  [0402]  108.47 58.71 120 bottom
C765  4.7uF  [0402]  117.13 53.71 120 bottom
C766  4.7uF  [0402]  124.82 69.15 300 bottom
C767  4.7uF  [0402]  115.39 53.71 120 bottom
C768  4.7uF  [0402]  107.5 53.71 240 bottom
C769  4.7uF  [0402]  124.05 67.15 60 bottom
C770  4.7uF  [0402]  124.05 64.71 120 bottom
C771  4.7uF  [0402]  124.05 58.71 120 bottom
C772  4.7uF  [0402]  124.05 61.15 60 bottom
C773  4.7uF  [0402]  124.05 62.71 120 bottom
C774  4.7uF  [0402]  124.05 65.71 120 bottom
C775  4.7uF  [0402]  124.05 56.71 120 bottom
C776  4.7uF  [0402]  115.39 70.15 60 bottom
C777  4.7uF  [0402]  117.13 70.15 60 bottom
C778  4.7uF  [0402]  108.47 62.71 120 bottom
C779  4.7uF  [0402]  123.09 68.15 300 bottom
C780  4.7uF  [0402]  118.86 70.15 60 bottom
C781  4.7uF  [0402]  111.93 54.15 60 bottom
C782  4.7uF  [0402]  107.5 65.71 240 bottom
C783  4.7uF  [0402]  109.24 61.71 240 bottom
C784  4.7uF  [0402]  107.5 63.71 240 bottom
C785  4.7uF  [0402]  107.5 59.71 240 bottom
C786  4.7uF  [0402]  107.5 57.71 240 bottom
C787  4.7uF  [0402]  107.5 55.71 240 bottom
C788  4.7uF  [0402]  113.66 54.15 60 bottom
C789  4.7uF  [0402]  107.5 66.71 240 bottom
C790  4.7uF  [0402]  113.66 69.71 120 bottom
C791  4.7uF  [0402]  111.93 69.71 120 bottom
C792  22uF  [0805]  120.4 64.09 90 bottom
C793  22uF  [0805]  120.4 66.25 90 bottom
C794  22uF  [0805]  120.4 61.93 90 bottom
C795  22uF  [0805]  120.4 59.77 90 bottom
C796  22uF  [0805]  111.77 66.25 270 bottom
C797  22uF  [0805]  111.77 64.09 270 bottom
C798  22uF  [0805]  135.27 87.93 180 top
C799  22uF  [0805]  111.77 57.61 270 bottom
C800  22uF  [0805]  111.77 59.77 270 bottom
C801  22uF  [0805]  120.4 57.61 90 bottom
C802  100uF  [1206]  105.67 87.58 270 bottom
C803  100uF  [1206]  99.35 86.93 0 top
C804  100uF  [1206]  111.64 39.83 180 bottom
C805  100uF  [1206]  106.23 36.53 90 top
C806  100uF  [1206]  101.35 35.77 90 bottom
C807  100uF  [1206]  108.08 87.58 270 bottom
C808  330uF  [1411]  158.76 78.06 180 bottom
C809  330uF  [1411]  158.76 63.83 180 bottom
C810  330uF  [1411]  111.39 35.38 270 bottom
C811  330uF  [1411]  158.76 74.5 180 bottom
C812  220uF  [1411]  100.34 88.6 90 bottom
C814  220uF  [1411]  158.76 56.72 180 bottom
C815  220uF  [1411]  158.76 60.28 180 bottom
C817  330uF  [1411]  158.76 70.94 180 bottom
C818  330uF  [1411]  158.76 49.61 180 bottom
C819  330uF  [1411]  158.76 67.39 180 bottom
C821  330uF  [1411]  158.76 46.05 180 bottom
C825  220uF  [1411]  158.76 53.16 180 bottom
C828  4.7uF  [0402]  108.47 69.71 120 bottom
C829  4.7uF  [0402]  108.47 68.71 120 bottom
C830  4.7uF  [0402]  108.47 67.71 120 bottom
C831  4.7uF  [0402]  110.2 69.15 60 bottom
C832  4.7uF  [0402]  110.2 70.15 60 bottom
C833  22uF  [0805]  79.28 67.77 0 top
C834  22uF  [0805]  83.1 67.73 0 top
C835  330uF  [1411]  85.42 72.72 90 bottom
C836  1uF  [0201]  123.01 54.1 30 bottom
C837  1uF  [0201]  124.74 54.75 330 bottom
C838  1uF  [0201]  124.74 53.75 330 bottom
C839  1uF  [0201]  146.63 46.93 90 top
C840  10uF  [0603]  147.58 44.27 0 top
C841  10uF  [0603]  142.03 35.43 0 top
C842  10uF  [0603]  145.23 35.43 180 top
C843  1uF  [0201]  100.49 60.1 210 bottom
C844  1uF  [0201]  102.49 64.25 30 bottom
C845  1uF  [0201]  102.49 63.25 30 bottom
C846  1uF  [0201]  102.49 62.25 30 bottom
C847  1uF  [0201]  102.49 58.25 30 bottom
C848  1uF  [0201]  102.49 57.25 30 bottom
C849  1uF  [0201]  102.49 56.25 30 bottom
C850  1uF  [0201]  101.62 61.1 330 bottom
C851  1uF  [0201]  101.62 59.75 30 bottom
C852  1uF  [0201]  101.62 58.75 30 bottom
C853  1uF  [0201]  101.06 55.78 270 bottom
C854  1uF  [0201]  100.49 57.1 210 bottom
C855  1uF  [0201]  100.49 62.1 210 bottom
C856  1uF  [0201]  101.06 64.08 90 bottom
C857  1uF  [0201]  85.8 52.33 90 top
C858  10uF  [0603]  87.8 49.93 270 bottom
C859  10uF  [0603]  88.02 61.93 270 bottom
C860  4.7uF  [0603]  84.5 45.13 270 top
C861  4.7uF  [0603]  87.8 52.93 90 bottom
C1196  220uF  [D2E]  80.8 48.82 270 top
C1197  220uF  [D2E]  73.16 47.96 270 bottom
C1199  100uF  [B2]  79.89 48.72 270 bottom
C1200  100uF  [B2]  89.65 36.43 0 top
C1201  1uF  [0201]  126.73 55.6 150 bottom
C1202  4.7uF  [0603]  129.61 56.43 0 bottom
C1203  1uF  [0201]  114.91 54.93 270 bottom
C1204  1uF  [0201]  118.38 68.93 90 bottom
C1205  1uF  [0201]  116.65 68.93 90 bottom
C1206  1uF  [0201]  120.11 68.93 90 bottom
C1207  1uF  [0201]  114.91 68.93 90 bottom
C1208  10uF  [0603]  146.06 88.98 180 top
C1209  10uF  [0603]  135.73 84.43 270 bottom
C1210  10uF  [0603]  150.74 69.73 180 bottom
C1211  1uF  [0201]  116.64 54.93 270 bottom
C1212  10uF  [0603]  137.43 84.43 270 bottom
C1213  100uF  [B2]  152.62 45.23 0 top
C1214  330uF  [1411]  141.69 88.03 180 top
C1215  330uF  [1411]  140.6 89.03 180 bottom
C1216  1uF  [0201]  112.88 51.25 210 bottom
C1217  1uF  [0201]  118.68 72.6 30 bottom
C1218  1uF  [0201]  114.61 51.25 210 bottom
C1219  1uF  [0201]  126.47 52.75 330 bottom
C1220  1uF  [0201]  125.87 51.75 210 bottom
C1222  100uF  [B2]  154.06 71.45 270 bottom
C1223  1uF  [0201]  116.95 72.6 30 bottom
C1224  1uF  [0201]  114.61 72.6 150 bottom
C1225  1uF  [0201]  118.68 51.25 330 bottom
C1227  100uF  [B2]  146.43 70.53 0 bottom
C1228  1uF  [0201]  129.33 62.75 210 bottom
C1229  1uF  [0201]  129.94 63.75 330 bottom
C1230  1uF  [0201]  128.47 63.25 210 bottom
C1231  1uF  [0201]  128.47 64.6 150 bottom
C1232  0.1uF  [0402]  129.15 61.21 240 bottom
C1233  0.1uF  [0402]  128.38 66.65 60 bottom
C1234  0.1uF  [0402]  129.15 60.21 240 bottom
C1235  4.7uF  [0402]  131.4 51.43 180 bottom
C1236  10uF  [0603]  84.5 51.43 270 top
C1237  1uF  [0201]  124.74 52.75 330 bottom
C1238  1uF  [0201]  124.14 51.75 210 bottom
C1239  1uF  [0201]  118.38 54.93 270 bottom
C1240  1uF  [0201]  120.11 54.93 270 bottom
C1241  10uF  [0603]  149.61 74.5 90 bottom
C1242  220uF  [D2E]  80.8 60.93 90 top
C1243  220uF  [D2E]  80.8 63.33 90 bottom
C1244  100uF  [0805]  85.3 66.3 180 top
C1245  100uF  [0805]  87.76 56.47 180 bottom
C1246  100uF  [0805]  85.35 61.42 0 top
C1247  22uF  [0603]  88.02 64.93 270 bottom
C1248  22uF  [0603]  82.9 57.08 180 bottom
C1249  10uF  [0402]  104.04 63.15 120 bottom
C1250  10uF  [0402]  103.27 55.71 300 bottom
C1251  1uF  [0201]  103.66 58.28 90 bottom
C1252  1uF  [0201]  103.96 56.75 330 bottom
C1253  1uF  [0201]  88.32 58.93 0 bottom
C1254  1uF  [0201]  88.32 59.93 0 bottom
C1255  1uF  [0201]  103.35 61.75 210 bottom
C1256  1uF  [0201]  105.95 57.25 210 bottom
C1257  1uF  [0201]  125.87 60.1 150 bottom
C1258  1uF  [0201]  125.87 59.1 150 bottom
C1259  1uF  [0201]  125.87 61.1 150 bottom
C1260  1uF  [0201]  105.08 55.75 210 bottom
C1261  1uF  [0201]  105.08 60.75 210 bottom
C1262  1uF  [0201]  105.95 64.25 210 bottom
C1263  1uF  [0201]  127.34 62.25 330 bottom
C1264  1uF  [0201]  126.73 64.6 150 bottom
C1265  1uF  [0201]  125.87 64.1 150 bottom
C1266  1uF  [0201]  143.63 53.1 270 bottom
C1267  1uF  [0201]  85.3 63.93 180 top
C1268  1uF  [0201]  85.8 48.51 90 top
C1269  1uF  [0201]  148.13 47.43 0 bottom
C1270  1uF  [0201]  126.73 61.6 150 bottom
C1271  1uF  [0201]  144.63 60.43 90 bottom
C1272  1uF  [0201]  145.13 75.43 0 bottom
C1273  1uF  [0201]  105.08 61.75 210 bottom
C1274  1uF  [0201]  106.25 63.08 270 bottom
C1275  1uF  [0201]  106.25 55.08 270 bottom
C1276  1uF  [0201]  125.61 55.25 150 bottom
C1277  1uF  [0201]  105.08 57.75 210 bottom
C1278  1uF  [0201]  105.08 54.75 210 bottom
C1279  1uF  [0201]  105.08 62.75 210 bottom
C1280  1uF  [0201]  81.8 55.43 270 bottom
C1281  1uF  [0201]  127.34 60.6 30 bottom
C1282  1uF  [0201]  105.95 60.25 210 bottom
C1283  1uF  [0201]  106.25 58.78 90 bottom
C1284  1uF  [0201]  125.87 63.1 150 bottom
C1285  1uF  [0201]  105.08 58.75 210 bottom
C1286  22uF  [0603]  117.61 58.12 270 bottom
C1287  22uF  [0603]  116.09 65.74 90 bottom
C1288  22uF  [0603]  117.61 65.74 90 bottom
C1289  22uF  [0603]  116.09 58.12 270 bottom
C1290  22uF  [0603]  114.56 58.12 270 bottom
C1291  22uF  [0603]  114.56 65.74 90 bottom
C1292  47uF  [0805]  151.14 46.94 90 bottom
C1293  47uF  [0805]  93.39 86.93 270 top
C1294  47uF  [0805]  80.78 72.21 0 top
C1295  47uF  [0805]  152.14 62.25 90 bottom
C1296  47uF  [0805]  83.07 72.21 0 top
C1297  47uF  [0805]  146.13 73.9 90 bottom
C1298  220uF  [D2E]  93.61 89.74 0 bottom
C1299  220uF  [D2E]  80.78 73.28 90 bottom
C1302  220uF  [D2E]  148.49 66.12 0 bottom
C1303  220uF  [D2E]  148.46 50.57 0 bottom
C1304  1uF  [0201]  131.06 64.1 150 bottom
C1305  1uF  [0201]  131.06 62.1 150 bottom
C1306  1uF  [0201]  130.2 61.6 150 bottom
C1307  1uF  [0201]  131.67 65.75 330 bottom
C1308  1uF  [0201]  131.67 60.75 330 bottom
C1309  4.7uF  [0201]  130.2 65.6 150 bottom
C1310  4.7uF  [0201]  131.67 62.75 330 bottom
C1311  4.7uF  [0201]  130.2 66.6 150 bottom
C1312  4.7uF  [0201]  131.06 67.1 150 bottom
C1313  4.7uF  [0201]  131.67 64.75 330 bottom
C1314  4.7uF  [0201]  145.63 62.43 270 bottom
C1315  220uF  [D2E]  148.49 55.83 0 bottom
C1317  1uF  [0201]  126.73 65.6 150 bottom
C1318  1uF  [0201]  127.34 63.6 30 bottom
C1319  1uF  [0201]  112.88 72.6 150 bottom
C1320  1uF  [0201]  116.34 51.25 210 bottom
C1321  10uF  [0603]  151.39 72.47 90 bottom
C1323  220uF  [D2E]  115.76 88.58 180 bottom
C1324  220uF  [D2E]  129.6 88.58 0 bottom
C1325  1uF  [0201]  123.01 70.75 330 bottom
C1326  1uF  [0201]  121.28 70.75 330 bottom
C1327  1uF  [0201]  119.55 70.75 330 bottom
C1328  1uF  [0201]  121.28 71.75 330 bottom
C1329  1uF  [0201]  119.55 71.75 330 bottom
C1330  4.7uF  [0201]  132.23 83.93 90 bottom
C1331  4.7uF  [0201]  130.5 83.93 90 bottom
C1332  4.7uF  [0201]  123.57 88.93 270 bottom
C1333  4.7uF  [0201]  133.97 83.93 90 bottom
C1334  4.7uF  [0201]  123.22 85.43 180 bottom
C1335  4.7uF  [0201]  115.78 72.28 90 bottom
C1336  4.7uF  [0201]  110.07 85.43 0 bottom
C1337  4.7uF  [0201]  133.61 85.43 180 bottom
C1338  4.7uF  [0201]  113.74 71.75 210 bottom
C1339  4.7uF  [0201]  125.66 85.43 0 bottom
C1340  1uF  [0201]  117.21 71.1 150 bottom
C1341  10uF  [0603]  132.11 87.43 270 top
C1342  10uF  [0603]  130.41 87.43 270 top
C1343  10uF  [0603]  128.71 87.43 270 top
C1344  10uF  [0603]  123.51 87.43 270 top
C1345  1uF  [0201]  120.46 85.43 0 bottom
C1346  1uF  [0201]  113.74 70.75 210 bottom
C1347  1uF  [0201]  110.58 72.28 90 bottom
C1348  1uF  [0201]  110.28 71.1 150 bottom
C1349  1uF  [0201]  128.42 85.43 180 bottom
C1350  4.7uF  [0201]  123.57 83.93 90 bottom
C1351  4.7uF  [0201]  112.83 85.43 180 bottom
C1352  4.7uF  [0201]  130.88 85.43 0 bottom
C1353  4.7uF  [0201]  123.01 71.75 330 bottom
C1354  4.7uF  [0201]  117.81 71.75 330 bottom
C1355  4.7uF  [0201]  115.48 71.1 150 bottom
C1356  4.7uF  [0201]  112.01 70.75 210 bottom
C1357  4.7uF  [0201]  126.47 53.75 330 bottom
C1358  4.7uF  [0201]  112.01 71.75 210 bottom
C1359  4.7uF  [0201]  115.26 85.43 0 bottom
C1360  1uF  [0201]  121.83 88.93 270 bottom
C1361  10uF  [0603]  121.81 87.43 270 top
C1362  10uF  [0603]  116.51 87.43 270 top
C1363  10uF  [0603]  114.81 87.43 270 top
C1364  10uF  [0603]  113.11 87.43 270 top
C1365  1uF  [0201]  121.84 83.93 90 bottom
C1366  1uF  [0201]  118.03 85.43 180 bottom
C1367  220uF  [D2E]  130.96 35.33 0 bottom
C1368  1uF  [0201]  125.31 39.93 270 bottom
C1369  1uF  [0201]  119.55 53.1 30 bottom
C1370  1uF  [0201]  119.55 52.1 30 bottom
C1371  1uF  [0201]  121.28 53.1 30 bottom
C1372  1uF  [0201]  121.28 52.1 30 bottom
C1373  4.7uF  [0201]  133.56 38.43 180 bottom
C1374  4.7uF  [0201]  118.38 39.93 270 bottom
C1375  4.7uF  [0201]  130.85 38.43 0 bottom
C1376  4.7uF  [0201]  115.26 38.43 0 bottom
C1377  4.7uF  [0201]  120.11 39.93 270 bottom
C1378  4.7uF  [0201]  135.7 37.93 270 bottom
C1379  4.7uF  [0201]  128.42 38.43 180 bottom
C1380  4.7uF  [0201]  136.8 37.93 270 bottom
C1381  4.7uF  [0201]  127.04 39.93 270 bottom
C1382  4.7uF  [0201]  116.65 39.93 270 bottom
C1383  1uF  [0201]  123.01 53.1 30 bottom
C1384  10uF  [0603]  130.41 36.43 90 top
C1385  10uF  [0603]  132.11 36.43 90 top
C1386  10uF  [0603]  125.34 36.43 90 top
C1387  10uF  [0603]  133.83 36.43 90 top
C1388  220uF  [D2E]  118.66 35.33 180 bottom
C1389  1uF  [0201]  123.01 52.1 30 bottom
C1390  1uF  [0201]  114.91 39.93 270 bottom
C1391  1uF  [0201]  123.22 38.43 180 bottom
C1392  1uF  [0201]  110.28 53.1 150 bottom
C1393  1uF  [0201]  118.03 38.43 180 bottom
C1394  4.7uF  [0201]  120.46 38.43 0 bottom
C1395  4.7uF  [0201]  117.51 51.58 270 bottom
C1396  4.7uF  [0201]  117.81 52.75 330 bottom
C1397  4.7uF  [0201]  116.08 52.75 330 bottom
C1398  4.7uF  [0201]  115.48 52.1 150 bottom
C1399  4.7uF  [0201]  113.74 52.1 150 bottom
C1400  4.7uF  [0201]  113.74 53.1 150 bottom
C1401  4.7uF  [0201]  112.01 53.1 150 bottom
C1402  4.7uF  [0201]  112.01 52.1 150 bottom
C1403  4.7uF  [0201]  110.28 52.1 150 bottom
C1404  1uF  [0201]  125.66 38.43 0 bottom
C1405  10uF  [0603]  123.64 36.43 90 top
C1406  10uF  [0603]  118.34 36.43 90 top
C1407  10uF  [0603]  116.64 36.43 90 top
C1408  10uF  [0603]  114.94 36.43 90 top
C1410  100uF  [1206]  151.55 59.65 180 bottom
C1421  1uF  [0201]  106.56 71.25 150 bottom
C1422  1uF  [0201]  106.82 69.1 150 bottom
C1423  10uF  [0603]  140.03 35.43 180 bottom
C1424  100uF  [B2]  137.33 36.43 180 top
C1425  100uF  [B2]  84.8 51.73 90 bottom
C1426  22uF  [1206]  65.82 46.15 0 bottom
C1427  22uF  [0805]  76.92 46.79 0 top
C1428  100uF  [B2]  85.42 66.93 270 bottom
C1429  100uF  [B2]  85.42 61.13 90 bottom
C1430  10uF  [0603]  88.02 67.93 90 bottom
C1431  10uF  [0603]  85.8 55.93 270 bottom
C1432  10uF  [0603]  88.5 70.93 270 bottom
C1433  10uF  [0603]  84.3 54.63 0 top
C1434  1uF  [0201]  113.18 68.08 270 bottom
C1435  1uF  [0201]  109.72 68.08 270 bottom
C1436  1uF  [0201]  111.45 55.78 90 bottom
C1437  1uF  [0201]  113.18 55.78 90 bottom
C1438  1uF  [0201]  121.28 55.1 30 bottom
C1439  1uF  [0201]  121.28 69.1 30 bottom
C1440  47uF  [0805]  76.92 46.79 0 bottom
C1441  100uF  [0805]  74.81 46.79 180 top
C1443  100uF  [B2]  65.82 49.2 180 bottom
C1445  100uF  [1206]  88.99 86.93 180 top
C1446  22uF  [0805]  148.13 62.45 90 top
C1447  22uF  [0805]  148.1 62.25 270 bottom
C1448  1uF  [0201]  82.8 55.43 270 bottom
C1449  1uF  [0201]  83.8 55.43 270 bottom
C1450  22uF  [0805]  85.3 57.43 0 top
C1472  1pF  [0402]  59.19 11 180 top
C1473  1pF  [0402]  65.03 11 0 bottom
C1474  1pF  [0402]  74.68 11 180 top
C1475  1pF  [0402]  77.73 11 0 bottom
C1476  1pF  [0402]  79.76 11 0 bottom
C1477  1pF  [0402]  125.61 11 180 top
C1478  1pF  [0402]  97.67 11 0 bottom
C1479  1pF  [0402]  61.6 11 180 top
C1480  1pF  [0402]  79.76 11 180 top
C1481  1pF  [0402]  95.64 11 180 top
C1482  1pF  [0402]  121.67 11 180 top
C1483  47uF  [0805]  166.38 59.51 90 bottom
C1484  47uF  [0805]  166.5 42.24 90 bottom
C1485  47uF  [0805]  166.38 73.46 90 bottom
C1486  47uF  [0805]  166.38 70.94 90 bottom
C1487  47uF  [0805]  166.38 54.94 90 bottom
C1488  47uF  [0805]  166.38 66.37 90 bottom
C1489  47uF  [0805]  166.38 48.08 90 bottom
C1490  47uF  [0805]  166.38 50.37 90 bottom
C1491  47uF  [0805]  166.38 80.6 90 bottom
C1492  47uF  [0805]  166.38 77.93 90 bottom
C1493  47uF  [0805]  166.5 44.53 90 bottom
C1494  47uF  [0805]  166.38 61.8 90 bottom
C1495  47uF  [0805]  108.46 36.53 0 bottom
C1496  47uF  [0805]  127.93 83.83 90 bottom
C1497  47uF  [0805]  97.36 84.93 180 bottom
C1498  47uF  [0805]  96.46 36.63 180 top
C1499  47uF  [0805]  106.31 38.94 180 bottom
C1500  47uF  [0805]  103.39 87.98 180 bottom
C1501  47uF  [0805]  100.21 39.93 270 bottom
C1502  47uF  [0805]  137.67 87.93 0 top
C1503  22uF  [0603]  103.64 87.94 270 top
C1504  22uF  [0603]  82.3 75.93 270 top
C1505  22uF  [0603]  93.86 85.43 270 bottom
C1506  22uF  [0603]  99.06 36.9 90 top
C1507  22uF  [0603]  80.8 75.93 270 top
C1508  22uF  [0603]  105.56 87.93 270 top
C1509  22uF  [0603]  84.8 74.93 180 top
C1510  22uF  [0603]  107.76 87.93 270 top
C1511  22uF  [0603]  102.73 83.93 270 bottom
C1512  22uF  [0603]  101.03 83.93 270 bottom
C1513  22uF  [0603]  95.51 85.43 270 bottom
C1514  22uF  [0603]  99.33 83.93 270 bottom
C1515  22uF  [0603]  100.97 36.91 90 top
C1516  22uF  [0603]  102.76 36.93 90 top
C1517  22uF  [0603]  119.26 86.44 0 top
C1518  4.7uF  [0402]  204.15 100.15 180 top
C1519  4.7uF  [0402]  204.03 104.85 270 top
C1520  0.1uF  [0402]  205.04 100.15 180 top
C1521  0.1uF  [0402]  202.32 100.15 180 top
C1522  0.1uF  [0402]  204.73 103.46 0 top
C1523  4.7uF  [0402]  203.21 100.15 180 top
C1524  DNI  [0402]  254.68 29.67 90 bottom
C1525  DNI  [0402]  33.41 46.24 90 bottom
C1550  0.1uF  [CAPC1005X60L20L]  218.7 19.26 180 bottom
C1654  0.1uF  [0402]  212.72 94.18 270 bottom
C1655  2.2uF  [0402]  209.12 94.58 270 bottom
C1656  470pF  [CAPC1005X60L20L]  211.52 90.9 90 bottom
C1659  2.2uF  [CC0603N]  205.37 94.57 90 top
C1660  100uF  [1206]  203.21 94.57 270 top
C1663  100uF  [1206]  205.62 94.57 270 bottom
C1665  100pF  [0402]  208.88 91.3 180 bottom
C1667  22uF  [1206]  212.3 97.28 270 bottom
C1669  22uF  [1206]  214.71 97.28 270 bottom
C1670  22uF  [1206]  215.17 96.8 270 top
C1673  1u  [CAPC1005X60L20L]  210.78 96.65 0 bottom
C1674  100uF  [1206]  203.21 94.57 270 bottom
C1816  1uF  [0402]  201.18 66.14 270 top
C1817  2.2uF  [CAPC1005X60L20L]  203.89 61.14 270 top
C1818  4.7uF  [0402]  203.92 60.2 270 top
C1819  2.2uF  [0603]  203.56 57.41 0 top
C1820  2.2uF  [0603]  202.6 57.94 270 bottom
C1821  330pF  [0603]  193.86 62.46 180 bottom
C1822  100pF  [0402]  193.53 62.44 90 top
C1823  2200pF  [0402]  194.19 61.34 90 bottom
C1824  330 uF  [CT7343-43_CUS]  193.91 85.88 270 top
C1825  330 uF  [CT7343-43_CUS]  193.61 71.07 270 top
C1826  330 uF  [CT7343-43_CUS]  192.56 57.38 270 top
C1827  330 uF  [CT7343-43_CUS]  192.08 41.15 270 top
C1829  22u  [CAPC3216X135L50N]  199.27 60.91 0 bottom
C1831  22u  [CAPC3216X135L50N]  199.27 63.58 0 bottom
C1832  22u  [CAPC3216X135L50N]  199.27 58.24 0 bottom
C1833  1u  [CAPC1005X60L20L]  186.49 78.29 270 top
C1834  1u  [CAPC1005X60L20L]  186.49 88.5 270 top
C1835  22u  [CAPC3216X135L50N]  193.4 80.11 180 top
C1836  22u  [CAPC3216X135L50N]  193.4 80.11 180 bottom
C1837  22u  [CAPC3216X135L50N]  190.28 88.52 90 top
C1838  22u  [CAPC3216X135L50N]  185.86 88.93 0 bottom
C1839  10uF  [0402]  188.53 82.68 0 bottom
C1840  1uF  [0402]  190.56 82.35 180 bottom
C1841  470uF  [CAPMP7343X300L130X240N_P079IN]  165.49 83.39 180 top
C1842  100u  [CAPC2012X110L50L]  175.52 84.48 90 bottom
C1843  100u  [CAPC2012X110L50L]  175.52 82.48 90 bottom
C1844  470uF  [CAPMP7343X300L130X240N_P079IN]  174.92 76.43 0 top
C1845  470uF  [CAPMP7343X300L130X240N_P079IN]  174.87 47.52 0 top
